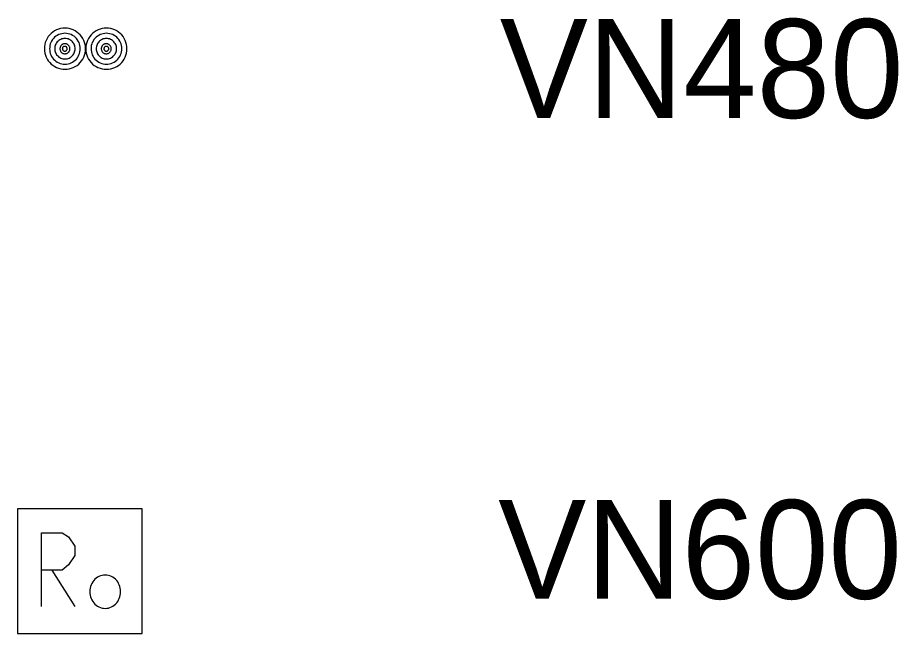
# Model space of a CAD drawing. Extents: x -592825 to -592404, y -1153473 to -1153230.
# Drawn here: x -592591.27 to -592577.89, y -1153410.54 to -1153401.19 of the extents above; entities that cross this region are included whole.
import ezdxf

# ---------------------------------------------------------------- set-up
doc = ezdxf.new("R2010")
doc.units = 0
doc.layers.add('Vrstva 45', color=7, linetype='Continuous')
doc.layers.add('Vrstva 63', color=7, linetype='Continuous')

msp = doc.modelspace()

# ---------------------------------------------------------------- linework, layer by layer
at = {"layer": 'Vrstva 45'}
for points in [[(-592590.235, -1153401.666), (-592590.237, -1153401.634), (-592590.241, -1153401.601), (-592590.25, -1153401.57), (-592590.262, -1153401.539), (-592590.277, -1153401.51), (-592590.295, -1153401.482), (-592590.315, -1153401.457), (-592590.339, -1153401.434), (-592590.364, -1153401.414), (-592590.391, -1153401.396), (-592590.42, -1153401.38), (-592590.451, -1153401.369), (-592590.483, -1153401.36), (-592590.515, -1153401.356), (-592590.547, -1153401.354), (-592590.58, -1153401.356), (-592590.613, -1153401.36), (-592590.643, -1153401.369), (-592590.675, -1153401.38), (-592590.704, -1153401.396), (-592590.731, -1153401.414), (-592590.756, -1153401.434), (-592590.779, -1153401.456), (-592590.801, -1153401.482), (-592590.817, -1153401.51), (-592590.833, -1153401.539), (-592590.845, -1153401.57), (-592590.853, -1153401.601), (-592590.859, -1153401.634), (-592590.859, -1153401.666), (-592590.858, -1153401.699), (-592590.853, -1153401.731), (-592590.844, -1153401.762), (-592590.833, -1153401.794), (-592590.817, -1153401.822), (-592590.8, -1153401.85), (-592590.779, -1153401.875), (-592590.756, -1153401.898), (-592590.731, -1153401.918), (-592590.703, -1153401.936), (-592590.675, -1153401.952), (-592590.643, -1153401.963), (-592590.612, -1153401.972), (-592590.58, -1153401.977), (-592590.547, -1153401.978), (-592590.515, -1153401.977), (-592590.482, -1153401.972), (-592590.451, -1153401.963), (-592590.42, -1153401.952), (-592590.391, -1153401.936), (-592590.363, -1153401.919), (-592590.338, -1153401.898), (-592590.315, -1153401.875), (-592590.295, -1153401.85), (-592590.277, -1153401.822), (-592590.261, -1153401.792), (-592590.25, -1153401.762), (-592590.241, -1153401.731), (-592590.237, -1153401.699), (-592590.235, -1153401.666)], [(-592590.314, -1153401.666), (-592590.315, -1153401.642), (-592590.319, -1153401.617), (-592590.325, -1153401.594), (-592590.333, -1153401.571), (-592590.345, -1153401.55), (-592590.359, -1153401.528), (-592590.373, -1153401.51), (-592590.391, -1153401.492), (-592590.409, -1153401.477), (-592590.431, -1153401.464), (-592590.453, -1153401.452), (-592590.475, -1153401.444), (-592590.499, -1153401.438), (-592590.523, -1153401.434), (-592590.547, -1153401.432), (-592590.571, -1153401.434), (-592590.595, -1153401.438), (-592590.619, -1153401.444), (-592590.642, -1153401.452), (-592590.664, -1153401.464), (-592590.685, -1153401.477), (-592590.704, -1153401.492), (-592590.721, -1153401.51), (-592590.737, -1153401.528), (-592590.749, -1153401.55), (-592590.761, -1153401.571), (-592590.769, -1153401.594), (-592590.775, -1153401.618), (-592590.779, -1153401.642), (-592590.781, -1153401.666), (-592590.779, -1153401.69), (-592590.776, -1153401.714), (-592590.769, -1153401.738), (-592590.761, -1153401.761), (-592590.749, -1153401.783), (-592590.736, -1153401.804), (-592590.721, -1153401.822), (-592590.703, -1153401.84), (-592590.685, -1153401.855), (-592590.664, -1153401.868), (-592590.642, -1153401.88), (-592590.62, -1153401.888), (-592590.595, -1153401.894), (-592590.572, -1153401.898), (-592590.547, -1153401.9), (-592590.523, -1153401.898), (-592590.499, -1153401.894), (-592590.475, -1153401.888), (-592590.452, -1153401.879), (-592590.431, -1153401.868), (-592590.41, -1153401.855), (-592590.391, -1153401.84), (-592590.374, -1153401.822), (-592590.358, -1153401.804), (-592590.345, -1153401.783), (-592590.334, -1153401.761), (-592590.325, -1153401.738), (-592590.319, -1153401.714), (-592590.315, -1153401.69), (-592590.314, -1153401.666)], [(-592589.605, -1153401.666), (-592589.607, -1153401.634), (-592589.611, -1153401.601), (-592589.621, -1153401.57), (-592589.631, -1153401.539), (-592589.647, -1153401.51), (-592589.665, -1153401.482), (-592589.685, -1153401.457), (-592589.709, -1153401.434), (-592589.733, -1153401.414), (-592589.761, -1153401.396), (-592589.791, -1153401.38), (-592589.821, -1153401.369), (-592589.852, -1153401.36), (-592589.885, -1153401.356), (-592589.917, -1153401.353), (-592589.951, -1153401.356), (-592589.982, -1153401.36), (-592590.013, -1153401.369), (-592590.044, -1153401.38), (-592590.073, -1153401.396), (-592590.101, -1153401.413), (-592590.127, -1153401.434), (-592590.15, -1153401.457), (-592590.171, -1153401.482), (-592590.189, -1153401.51), (-592590.203, -1153401.539), (-592590.215, -1153401.57), (-592590.223, -1153401.601), (-592590.228, -1153401.634), (-592590.229, -1153401.666), (-592590.229, -1153401.699), (-592590.223, -1153401.731), (-592590.215, -1153401.762), (-592590.203, -1153401.794), (-592590.188, -1153401.822), (-592590.171, -1153401.85), (-592590.149, -1153401.875), (-592590.127, -1153401.898), (-592590.101, -1153401.919), (-592590.074, -1153401.936), (-592590.045, -1153401.952), (-592590.014, -1153401.963), (-592589.982, -1153401.972), (-592589.951, -1153401.977), (-592589.917, -1153401.978), (-592589.885, -1153401.976), (-592589.852, -1153401.972), (-592589.821, -1153401.963), (-592589.79, -1153401.952), (-592589.761, -1153401.936), (-592589.733, -1153401.919), (-592589.709, -1153401.898), (-592589.685, -1153401.875), (-592589.665, -1153401.85), (-592589.647, -1153401.822), (-592589.631, -1153401.792), (-592589.62, -1153401.762), (-592589.612, -1153401.731), (-592589.607, -1153401.699), (-592589.605, -1153401.666)], [(-592589.683, -1153401.666), (-592589.685, -1153401.642), (-592589.689, -1153401.618), (-592589.695, -1153401.594), (-592589.703, -1153401.571), (-592589.715, -1153401.55), (-592589.728, -1153401.528), (-592589.744, -1153401.51), (-592589.761, -1153401.492), (-592589.781, -1153401.477), (-592589.8, -1153401.463), (-592589.822, -1153401.452), (-592589.845, -1153401.444), (-592589.869, -1153401.438), (-592589.893, -1153401.434), (-592589.917, -1153401.432), (-592589.941, -1153401.434), (-592589.967, -1153401.438), (-592589.989, -1153401.444), (-592590.013, -1153401.452), (-592590.034, -1153401.463), (-592590.055, -1153401.476), (-592590.073, -1153401.492), (-592590.091, -1153401.509), (-592590.107, -1153401.528), (-592590.119, -1153401.55), (-592590.131, -1153401.571), (-592590.139, -1153401.594), (-592590.147, -1153401.618), (-592590.149, -1153401.642), (-592590.151, -1153401.666), (-592590.15, -1153401.69), (-592590.146, -1153401.714), (-592590.139, -1153401.738), (-592590.131, -1153401.761), (-592590.119, -1153401.783), (-592590.107, -1153401.804), (-592590.091, -1153401.822), (-592590.073, -1153401.84), (-592590.055, -1153401.855), (-592590.034, -1153401.868), (-592590.012, -1153401.88), (-592589.989, -1153401.888), (-592589.966, -1153401.894), (-592589.941, -1153401.898), (-592589.917, -1153401.9), (-592589.893, -1153401.898), (-592589.869, -1153401.894), (-592589.845, -1153401.888), (-592589.823, -1153401.88), (-592589.8, -1153401.868), (-592589.78, -1153401.855), (-592589.761, -1153401.84), (-592589.743, -1153401.822), (-592589.728, -1153401.804), (-592589.715, -1153401.783), (-592589.703, -1153401.761), (-592589.695, -1153401.738), (-592589.689, -1153401.714), (-592589.685, -1153401.69), (-592589.683, -1153401.666)], [(-592590.393, -1153401.666), (-592590.393, -1153401.65), (-592590.395, -1153401.634), (-592590.399, -1153401.618), (-592590.406, -1153401.603), (-592590.413, -1153401.588), (-592590.422, -1153401.575), (-592590.433, -1153401.562), (-592590.443, -1153401.551), (-592590.456, -1153401.54), (-592590.469, -1153401.532), (-592590.484, -1153401.524), (-592590.499, -1153401.518), (-592590.515, -1153401.514), (-592590.531, -1153401.512), (-592590.547, -1153401.511), (-592590.563, -1153401.512), (-592590.579, -1153401.514), (-592590.595, -1153401.518), (-592590.61, -1153401.524), (-592590.625, -1153401.532), (-592590.639, -1153401.54), (-592590.651, -1153401.551), (-592590.663, -1153401.563), (-592590.673, -1153401.575), (-592590.681, -1153401.588), (-592590.689, -1153401.603), (-592590.695, -1153401.618), (-592590.699, -1153401.634), (-592590.702, -1153401.65), (-592590.702, -1153401.666), (-592590.701, -1153401.682), (-592590.699, -1153401.698), (-592590.695, -1153401.714), (-592590.689, -1153401.729), (-592590.682, -1153401.744), (-592590.673, -1153401.757), (-592590.662, -1153401.77), (-592590.651, -1153401.781), (-592590.639, -1153401.792), (-592590.625, -1153401.8), (-592590.61, -1153401.808), (-592590.595, -1153401.814), (-592590.58, -1153401.818), (-592590.564, -1153401.82), (-592590.547, -1153401.821), (-592590.531, -1153401.82), (-592590.515, -1153401.818), (-592590.499, -1153401.814), (-592590.485, -1153401.808), (-592590.469, -1153401.8), (-592590.456, -1153401.792), (-592590.443, -1153401.781), (-592590.432, -1153401.77), (-592590.422, -1153401.757), (-592590.413, -1153401.744), (-592590.405, -1153401.728), (-592590.4, -1153401.714), (-592590.395, -1153401.698), (-592590.393, -1153401.682), (-592590.393, -1153401.666)], [(-592590.471, -1153401.666), (-592590.471, -1153401.658), (-592590.473, -1153401.65), (-592590.475, -1153401.642), (-592590.477, -1153401.635), (-592590.481, -1153401.628), (-592590.486, -1153401.622), (-592590.491, -1153401.615), (-592590.496, -1153401.61), (-592590.503, -1153401.604), (-592590.509, -1153401.6), (-592590.517, -1153401.596), (-592590.524, -1153401.594), (-592590.531, -1153401.592), (-592590.539, -1153401.59), (-592590.547, -1153401.59), (-592590.555, -1153401.59), (-592590.563, -1153401.592), (-592590.571, -1153401.594), (-592590.579, -1153401.596), (-592590.585, -1153401.6), (-592590.592, -1153401.604), (-592590.598, -1153401.61), (-592590.605, -1153401.615), (-592590.609, -1153401.622), (-592590.613, -1153401.628), (-592590.617, -1153401.635), (-592590.619, -1153401.642), (-592590.622, -1153401.65), (-592590.623, -1153401.658), (-592590.623, -1153401.666), (-592590.623, -1153401.674), (-592590.621, -1153401.682), (-592590.619, -1153401.69), (-592590.617, -1153401.697), (-592590.613, -1153401.704), (-592590.609, -1153401.711), (-592590.605, -1153401.717), (-592590.598, -1153401.723), (-592590.592, -1153401.728), (-592590.585, -1153401.732), (-592590.578, -1153401.736), (-592590.571, -1153401.738), (-592590.563, -1153401.74), (-592590.555, -1153401.742), (-592590.547, -1153401.742), (-592590.539, -1153401.742), (-592590.531, -1153401.74), (-592590.523, -1153401.738), (-592590.516, -1153401.736), (-592590.509, -1153401.732), (-592590.503, -1153401.728), (-592590.497, -1153401.723), (-592590.491, -1153401.717), (-592590.485, -1153401.711), (-592590.481, -1153401.704), (-592590.478, -1153401.697), (-592590.475, -1153401.69), (-592590.473, -1153401.682), (-592590.471, -1153401.674), (-592590.471, -1153401.666)], [(-592589.762, -1153401.666), (-592589.763, -1153401.65), (-592589.766, -1153401.634), (-592589.769, -1153401.618), (-592589.775, -1153401.603), (-592589.783, -1153401.588), (-592589.792, -1153401.575), (-592589.802, -1153401.562), (-592589.814, -1153401.551), (-592589.826, -1153401.54), (-592589.84, -1153401.532), (-592589.855, -1153401.524), (-592589.869, -1153401.518), (-592589.885, -1153401.514), (-592589.901, -1153401.512), (-592589.917, -1153401.511), (-592589.934, -1153401.512), (-592589.949, -1153401.514), (-592589.965, -1153401.518), (-592589.98, -1153401.524), (-592589.995, -1153401.532), (-592590.008, -1153401.54), (-592590.021, -1153401.551), (-592590.033, -1153401.562), (-592590.043, -1153401.575), (-592590.051, -1153401.588), (-592590.059, -1153401.603), (-592590.065, -1153401.618), (-592590.069, -1153401.634), (-592590.071, -1153401.65), (-592590.072, -1153401.666), (-592590.071, -1153401.682), (-592590.069, -1153401.698), (-592590.065, -1153401.714), (-592590.059, -1153401.729), (-592590.052, -1153401.744), (-592590.043, -1153401.757), (-592590.033, -1153401.77), (-592590.021, -1153401.781), (-592590.008, -1153401.792), (-592589.995, -1153401.8), (-592589.981, -1153401.808), (-592589.965, -1153401.814), (-592589.949, -1153401.817), (-592589.933, -1153401.82), (-592589.917, -1153401.821), (-592589.901, -1153401.82), (-592589.885, -1153401.818), (-592589.869, -1153401.814), (-592589.854, -1153401.808), (-592589.839, -1153401.8), (-592589.826, -1153401.792), (-592589.814, -1153401.781), (-592589.802, -1153401.77), (-592589.791, -1153401.756), (-592589.783, -1153401.744), (-592589.775, -1153401.729), (-592589.77, -1153401.714), (-592589.765, -1153401.698), (-592589.763, -1153401.682), (-592589.762, -1153401.666)], [(-592589.843, -1153401.666), (-592589.843, -1153401.658), (-592589.845, -1153401.65), (-592589.847, -1153401.642), (-592589.851, -1153401.635), (-592589.853, -1153401.628), (-592589.859, -1153401.622), (-592589.863, -1153401.615), (-592589.869, -1153401.61), (-592589.875, -1153401.604), (-592589.881, -1153401.6), (-592589.889, -1153401.596), (-592589.896, -1153401.594), (-592589.904, -1153401.592), (-592589.911, -1153401.59), (-592589.919, -1153401.59), (-592589.927, -1153401.59), (-592589.935, -1153401.592), (-592589.943, -1153401.594), (-592589.951, -1153401.596), (-592589.957, -1153401.6), (-592589.965, -1153401.604), (-592589.971, -1153401.61), (-592589.977, -1153401.615), (-592589.981, -1153401.622), (-592589.985, -1153401.628), (-592589.989, -1153401.635), (-592589.993, -1153401.642), (-592589.994, -1153401.65), (-592589.995, -1153401.658), (-592589.996, -1153401.666), (-592589.995, -1153401.674), (-592589.994, -1153401.682), (-592589.993, -1153401.69), (-592589.989, -1153401.697), (-592589.985, -1153401.704), (-592589.982, -1153401.711), (-592589.977, -1153401.716), (-592589.971, -1153401.723), (-592589.965, -1153401.728), (-592589.957, -1153401.732), (-592589.951, -1153401.736), (-592589.943, -1153401.738), (-592589.935, -1153401.74), (-592589.927, -1153401.742), (-592589.919, -1153401.742), (-592589.911, -1153401.742), (-592589.903, -1153401.74), (-592589.897, -1153401.738), (-592589.889, -1153401.736), (-592589.881, -1153401.732), (-592589.875, -1153401.728), (-592589.869, -1153401.723), (-592589.863, -1153401.717), (-592589.859, -1153401.711), (-592589.853, -1153401.704), (-592589.85, -1153401.696), (-592589.847, -1153401.69), (-592589.845, -1153401.682), (-592589.843, -1153401.674), (-592589.843, -1153401.666)], [(-592590.513, -1153401.666), (-592590.513, -1153401.662), (-592590.513, -1153401.658), (-592590.515, -1153401.654), (-592590.516, -1153401.651), (-592590.518, -1153401.648), (-592590.52, -1153401.644), (-592590.522, -1153401.642), (-592590.525, -1153401.638), (-592590.529, -1153401.636), (-592590.531, -1153401.634), (-592590.535, -1153401.632), (-592590.538, -1153401.631), (-592590.542, -1153401.63), (-592590.545, -1153401.63), (-592590.55, -1153401.629), (-592590.554, -1153401.63), (-592590.557, -1153401.63), (-592590.561, -1153401.631), (-592590.565, -1153401.632), (-592590.569, -1153401.634), (-592590.571, -1153401.636), (-592590.575, -1153401.638), (-592590.577, -1153401.642), (-592590.579, -1153401.644), (-592590.582, -1153401.648), (-592590.583, -1153401.651), (-592590.585, -1153401.654), (-592590.585, -1153401.658), (-592590.586, -1153401.662), (-592590.587, -1153401.666), (-592590.586, -1153401.67), (-592590.586, -1153401.674), (-592590.585, -1153401.678), (-592590.583, -1153401.681), (-592590.581, -1153401.684), (-592590.579, -1153401.688), (-592590.577, -1153401.69), (-592590.575, -1153401.694), (-592590.571, -1153401.696), (-592590.569, -1153401.698), (-592590.565, -1153401.7), (-592590.561, -1153401.701), (-592590.557, -1153401.702), (-592590.553, -1153401.703), (-592590.549, -1153401.703), (-592590.545, -1153401.703), (-592590.542, -1153401.702), (-592590.539, -1153401.701), (-592590.535, -1153401.7), (-592590.531, -1153401.698), (-592590.529, -1153401.696), (-592590.525, -1153401.694), (-592590.523, -1153401.69), (-592590.519, -1153401.688), (-592590.517, -1153401.684), (-592590.516, -1153401.681), (-592590.515, -1153401.678), (-592590.514, -1153401.674), (-592590.513, -1153401.67), (-592590.513, -1153401.666)], [(-592590.235, -1153401.686), (-592590.235, -1153401.646)], [(-592589.881, -1153401.666), (-592589.881, -1153401.662), (-592589.881, -1153401.658), (-592589.882, -1153401.654), (-592589.883, -1153401.651), (-592589.885, -1153401.648), (-592589.888, -1153401.644), (-592589.89, -1153401.642), (-592589.893, -1153401.638), (-592589.895, -1153401.636), (-592589.899, -1153401.634), (-592589.903, -1153401.632), (-592589.906, -1153401.631), (-592589.91, -1153401.63), (-592589.914, -1153401.629), (-592589.917, -1153401.629), (-592589.921, -1153401.63), (-592589.925, -1153401.63), (-592589.929, -1153401.631), (-592589.932, -1153401.632), (-592589.935, -1153401.634), (-592589.939, -1153401.636), (-592589.942, -1153401.638), (-592589.945, -1153401.642), (-592589.947, -1153401.644), (-592589.949, -1153401.648), (-592589.951, -1153401.651), (-592589.952, -1153401.654), (-592589.953, -1153401.658), (-592589.955, -1153401.662), (-592589.955, -1153401.666), (-592589.955, -1153401.67), (-592589.954, -1153401.674), (-592589.952, -1153401.678), (-592589.951, -1153401.681), (-592589.949, -1153401.684), (-592589.947, -1153401.688), (-592589.945, -1153401.69), (-592589.942, -1153401.694), (-592589.939, -1153401.696), (-592589.935, -1153401.698), (-592589.933, -1153401.7), (-592589.929, -1153401.701), (-592589.925, -1153401.702), (-592589.921, -1153401.703), (-592589.917, -1153401.703), (-592589.913, -1153401.702), (-592589.91, -1153401.702), (-592589.906, -1153401.701), (-592589.902, -1153401.7), (-592589.899, -1153401.698), (-592589.896, -1153401.696), (-592589.893, -1153401.694), (-592589.889, -1153401.69), (-592589.888, -1153401.688), (-592589.885, -1153401.684), (-592589.883, -1153401.681), (-592589.882, -1153401.678), (-592589.881, -1153401.674), (-592589.881, -1153401.67), (-592589.881, -1153401.666)], [(-592589.376, -1153408.653), (-592591.266, -1153408.653)], [(-592591.266, -1153408.653), (-592591.266, -1153410.543)], [(-592589.376, -1153410.543), (-592589.376, -1153408.653)], [(-592590.903, -1153409.016), (-592590.589, -1153409.016)], [(-592590.903, -1153410.134), (-592590.903, -1153409.016)], [(-592590.903, -1153409.016), (-592590.589, -1153409.016)], [(-592590.903, -1153410.134), (-592590.903, -1153409.016)], [(-592590.903, -1153409.016), (-592590.589, -1153409.016)], [(-592590.903, -1153410.134), (-592590.903, -1153409.016)], [(-592590.903, -1153409.016), (-592590.589, -1153409.016)], [(-592590.903, -1153410.134), (-592590.903, -1153409.016)], [(-592590.589, -1153409.016), (-592590.494, -1153409.078)], [(-592590.589, -1153409.016), (-592590.494, -1153409.078)], [(-592590.589, -1153409.016), (-592590.494, -1153409.078)], [(-592590.589, -1153409.016), (-592590.494, -1153409.078)], [(-592590.494, -1153409.078), (-592590.399, -1153409.22)], [(-592590.494, -1153409.078), (-592590.399, -1153409.22)], [(-592590.494, -1153409.078), (-592590.399, -1153409.22)], [(-592590.494, -1153409.078), (-592590.399, -1153409.22)], [(-592590.399, -1153409.22), (-592590.399, -1153409.362)], [(-592590.399, -1153409.22), (-592590.399, -1153409.362)], [(-592590.399, -1153409.22), (-592590.399, -1153409.362)], [(-592590.399, -1153409.22), (-592590.399, -1153409.362)], [(-592590.399, -1153409.362), (-592590.494, -1153409.503)], [(-592590.399, -1153409.362), (-592590.494, -1153409.503)], [(-592590.399, -1153409.362), (-592590.494, -1153409.503)], [(-592590.399, -1153409.362), (-592590.494, -1153409.503)], [(-592590.589, -1153409.582), (-592590.903, -1153409.582)], [(-592590.589, -1153409.582), (-592590.903, -1153409.582)], [(-592590.589, -1153409.582), (-592590.903, -1153409.582)], [(-592590.589, -1153409.582), (-592590.903, -1153409.582)], [(-592590.746, -1153409.582), (-592590.399, -1153410.134)], [(-592590.746, -1153409.582), (-592590.399, -1153410.134)], [(-592590.746, -1153409.582), (-592590.399, -1153410.134)], [(-592590.746, -1153409.582), (-592590.399, -1153410.134)], [(-592590.494, -1153409.503), (-592590.589, -1153409.582)], [(-592590.494, -1153409.503), (-592590.589, -1153409.582)], [(-592590.494, -1153409.503), (-592590.589, -1153409.582)], [(-592590.494, -1153409.503), (-592590.589, -1153409.582)], [(-592589.701, -1153409.91), (-592589.702, -1153409.884), (-592589.706, -1153409.858), (-592589.712, -1153409.832), (-592589.721, -1153409.808), (-592589.732, -1153409.784), (-592589.746, -1153409.762), (-592589.761, -1153409.741), (-592589.779, -1153409.722), (-592589.797, -1153409.706), (-592589.818, -1153409.691), (-592589.84, -1153409.68), (-592589.863, -1153409.67), (-592589.887, -1153409.663), (-592589.911, -1153409.659), (-592589.935, -1153409.658), (-592589.96, -1153409.659), (-592589.984, -1153409.663), (-592590.008, -1153409.67), (-592590.031, -1153409.68), (-592590.053, -1153409.691), (-592590.073, -1153409.706), (-592590.093, -1153409.722), (-592590.109, -1153409.741), (-592590.125, -1153409.762), (-592590.139, -1153409.784), (-592590.149, -1153409.808), (-592590.159, -1153409.832), (-592590.165, -1153409.858), (-592590.169, -1153409.884), (-592590.17, -1153409.91), (-592590.169, -1153409.937), (-592590.165, -1153409.963), (-592590.159, -1153409.988), (-592590.149, -1153410.013), (-592590.139, -1153410.036), (-592590.125, -1153410.059), (-592590.109, -1153410.08), (-592590.093, -1153410.098), (-592590.073, -1153410.114), (-592590.053, -1153410.129), (-592590.031, -1153410.141), (-592590.008, -1153410.151), (-592589.984, -1153410.158), (-592589.96, -1153410.162), (-592589.935, -1153410.163), (-592589.911, -1153410.162), (-592589.887, -1153410.158), (-592589.863, -1153410.151), (-592589.84, -1153410.141), (-592589.818, -1153410.129), (-592589.797, -1153410.114), (-592589.779, -1153410.098), (-592589.761, -1153410.08), (-592589.746, -1153410.059), (-592589.732, -1153410.036), (-592589.721, -1153410.013), (-592589.712, -1153409.988), (-592589.706, -1153409.963), (-592589.702, -1153409.937), (-592589.701, -1153409.91)], [(-592589.701, -1153409.91), (-592589.702, -1153409.884), (-592589.706, -1153409.858), (-592589.712, -1153409.832), (-592589.721, -1153409.808), (-592589.732, -1153409.784), (-592589.746, -1153409.762), (-592589.761, -1153409.741), (-592589.779, -1153409.722), (-592589.797, -1153409.706), (-592589.818, -1153409.691), (-592589.84, -1153409.68), (-592589.863, -1153409.67), (-592589.887, -1153409.663), (-592589.911, -1153409.659), (-592589.935, -1153409.658), (-592589.96, -1153409.659), (-592589.984, -1153409.663), (-592590.008, -1153409.67), (-592590.031, -1153409.68), (-592590.053, -1153409.691), (-592590.073, -1153409.706), (-592590.093, -1153409.722), (-592590.109, -1153409.741), (-592590.125, -1153409.762), (-592590.139, -1153409.784), (-592590.149, -1153409.808), (-592590.159, -1153409.832), (-592590.165, -1153409.858), (-592590.169, -1153409.884), (-592590.17, -1153409.91), (-592590.169, -1153409.937), (-592590.165, -1153409.963), (-592590.159, -1153409.988), (-592590.149, -1153410.013), (-592590.139, -1153410.036), (-592590.125, -1153410.059), (-592590.109, -1153410.08), (-592590.093, -1153410.098), (-592590.073, -1153410.114), (-592590.053, -1153410.129), (-592590.031, -1153410.141), (-592590.008, -1153410.151), (-592589.984, -1153410.158), (-592589.96, -1153410.162), (-592589.935, -1153410.163), (-592589.911, -1153410.162), (-592589.887, -1153410.158), (-592589.863, -1153410.151), (-592589.84, -1153410.141), (-592589.818, -1153410.129), (-592589.797, -1153410.114), (-592589.779, -1153410.098), (-592589.761, -1153410.08), (-592589.746, -1153410.059), (-592589.732, -1153410.036), (-592589.721, -1153410.013), (-592589.712, -1153409.988), (-592589.706, -1153409.963), (-592589.702, -1153409.937), (-592589.701, -1153409.91)], [(-592589.701, -1153409.91), (-592589.702, -1153409.884), (-592589.706, -1153409.858), (-592589.712, -1153409.832), (-592589.721, -1153409.808), (-592589.732, -1153409.784), (-592589.746, -1153409.762), (-592589.761, -1153409.741), (-592589.779, -1153409.722), (-592589.797, -1153409.706), (-592589.818, -1153409.691), (-592589.84, -1153409.68), (-592589.863, -1153409.67), (-592589.887, -1153409.663), (-592589.911, -1153409.659), (-592589.935, -1153409.658), (-592589.96, -1153409.659), (-592589.984, -1153409.663), (-592590.008, -1153409.67), (-592590.031, -1153409.68), (-592590.053, -1153409.691), (-592590.073, -1153409.706), (-592590.093, -1153409.722), (-592590.109, -1153409.741), (-592590.125, -1153409.762), (-592590.139, -1153409.784), (-592590.149, -1153409.808), (-592590.159, -1153409.832), (-592590.165, -1153409.858), (-592590.169, -1153409.884), (-592590.17, -1153409.91), (-592590.169, -1153409.937), (-592590.165, -1153409.963), (-592590.159, -1153409.988), (-592590.149, -1153410.013), (-592590.139, -1153410.036), (-592590.125, -1153410.059), (-592590.109, -1153410.08), (-592590.093, -1153410.098), (-592590.073, -1153410.114), (-592590.053, -1153410.129), (-592590.031, -1153410.141), (-592590.008, -1153410.151), (-592589.984, -1153410.158), (-592589.96, -1153410.162), (-592589.935, -1153410.163), (-592589.911, -1153410.162), (-592589.887, -1153410.158), (-592589.863, -1153410.151), (-592589.84, -1153410.141), (-592589.818, -1153410.129), (-592589.797, -1153410.114), (-592589.779, -1153410.098), (-592589.761, -1153410.08), (-592589.746, -1153410.059), (-592589.732, -1153410.036), (-592589.721, -1153410.013), (-592589.712, -1153409.988), (-592589.706, -1153409.963), (-592589.702, -1153409.937), (-592589.701, -1153409.91)], [(-592589.701, -1153409.91), (-592589.702, -1153409.884), (-592589.706, -1153409.858), (-592589.712, -1153409.832), (-592589.721, -1153409.808), (-592589.732, -1153409.784), (-592589.746, -1153409.762), (-592589.761, -1153409.741), (-592589.779, -1153409.722), (-592589.797, -1153409.706), (-592589.818, -1153409.691), (-592589.84, -1153409.68), (-592589.863, -1153409.67), (-592589.887, -1153409.663), (-592589.911, -1153409.659), (-592589.935, -1153409.658), (-592589.96, -1153409.659), (-592589.984, -1153409.663), (-592590.008, -1153409.67), (-592590.031, -1153409.68), (-592590.053, -1153409.691), (-592590.073, -1153409.706), (-592590.093, -1153409.722), (-592590.109, -1153409.741), (-592590.125, -1153409.762), (-592590.139, -1153409.784), (-592590.149, -1153409.808), (-592590.159, -1153409.832), (-592590.165, -1153409.858), (-592590.169, -1153409.884), (-592590.17, -1153409.91), (-592590.169, -1153409.937), (-592590.165, -1153409.963), (-592590.159, -1153409.988), (-592590.149, -1153410.013), (-592590.139, -1153410.036), (-592590.125, -1153410.059), (-592590.109, -1153410.08), (-592590.093, -1153410.098), (-592590.073, -1153410.114), (-592590.053, -1153410.129), (-592590.031, -1153410.141), (-592590.008, -1153410.151), (-592589.984, -1153410.158), (-592589.96, -1153410.162), (-592589.935, -1153410.163), (-592589.911, -1153410.162), (-592589.887, -1153410.158), (-592589.863, -1153410.151), (-592589.84, -1153410.141), (-592589.818, -1153410.129), (-592589.797, -1153410.114), (-592589.779, -1153410.098), (-592589.761, -1153410.08), (-592589.746, -1153410.059), (-592589.732, -1153410.036), (-592589.721, -1153410.013), (-592589.712, -1153409.988), (-592589.706, -1153409.963), (-592589.702, -1153409.937), (-592589.701, -1153409.91)], [(-592591.266, -1153410.543), (-592589.376, -1153410.543)]]:
    msp.add_lwpolyline(points, dxfattribs=at)

# ---------------------------------------------------------------- texts
at = {"layer": 'Vrstva 63'}
for s, p in [('VN480', (-592583.941, -1153402.716)), ('VN600', (-592583.965, -1153410.018))]:
    msp.add_text(s, height=1.5, dxfattribs=at).set_placement(p)

doc.saveas('drawing.dxf')
